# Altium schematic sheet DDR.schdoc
size 420 x 297 mm; Symbol: Drawing-Symbol_A4; Company: 嘉立创EDA; Version: V1.0; Page Size: A4; @Project Name: A113 Android MircroPhone; @Page Count: 4; @Update Date: 2025-09-30; @Create Date: 2025-08-09; @Schematic Name: Schematic1; @Page No: 2; @Page Name: DDR; @Create Time: 14:16:37; @Update Time: 17:41:18; Border: 1; Width: 1655; Height: 1170; Region Start: 1; X Region Count: 6; Y Region Count: 4; Blade Width: 10; Title Block Position: 3; @Board Name: Board1; Device: Drawing-Symbol_A4
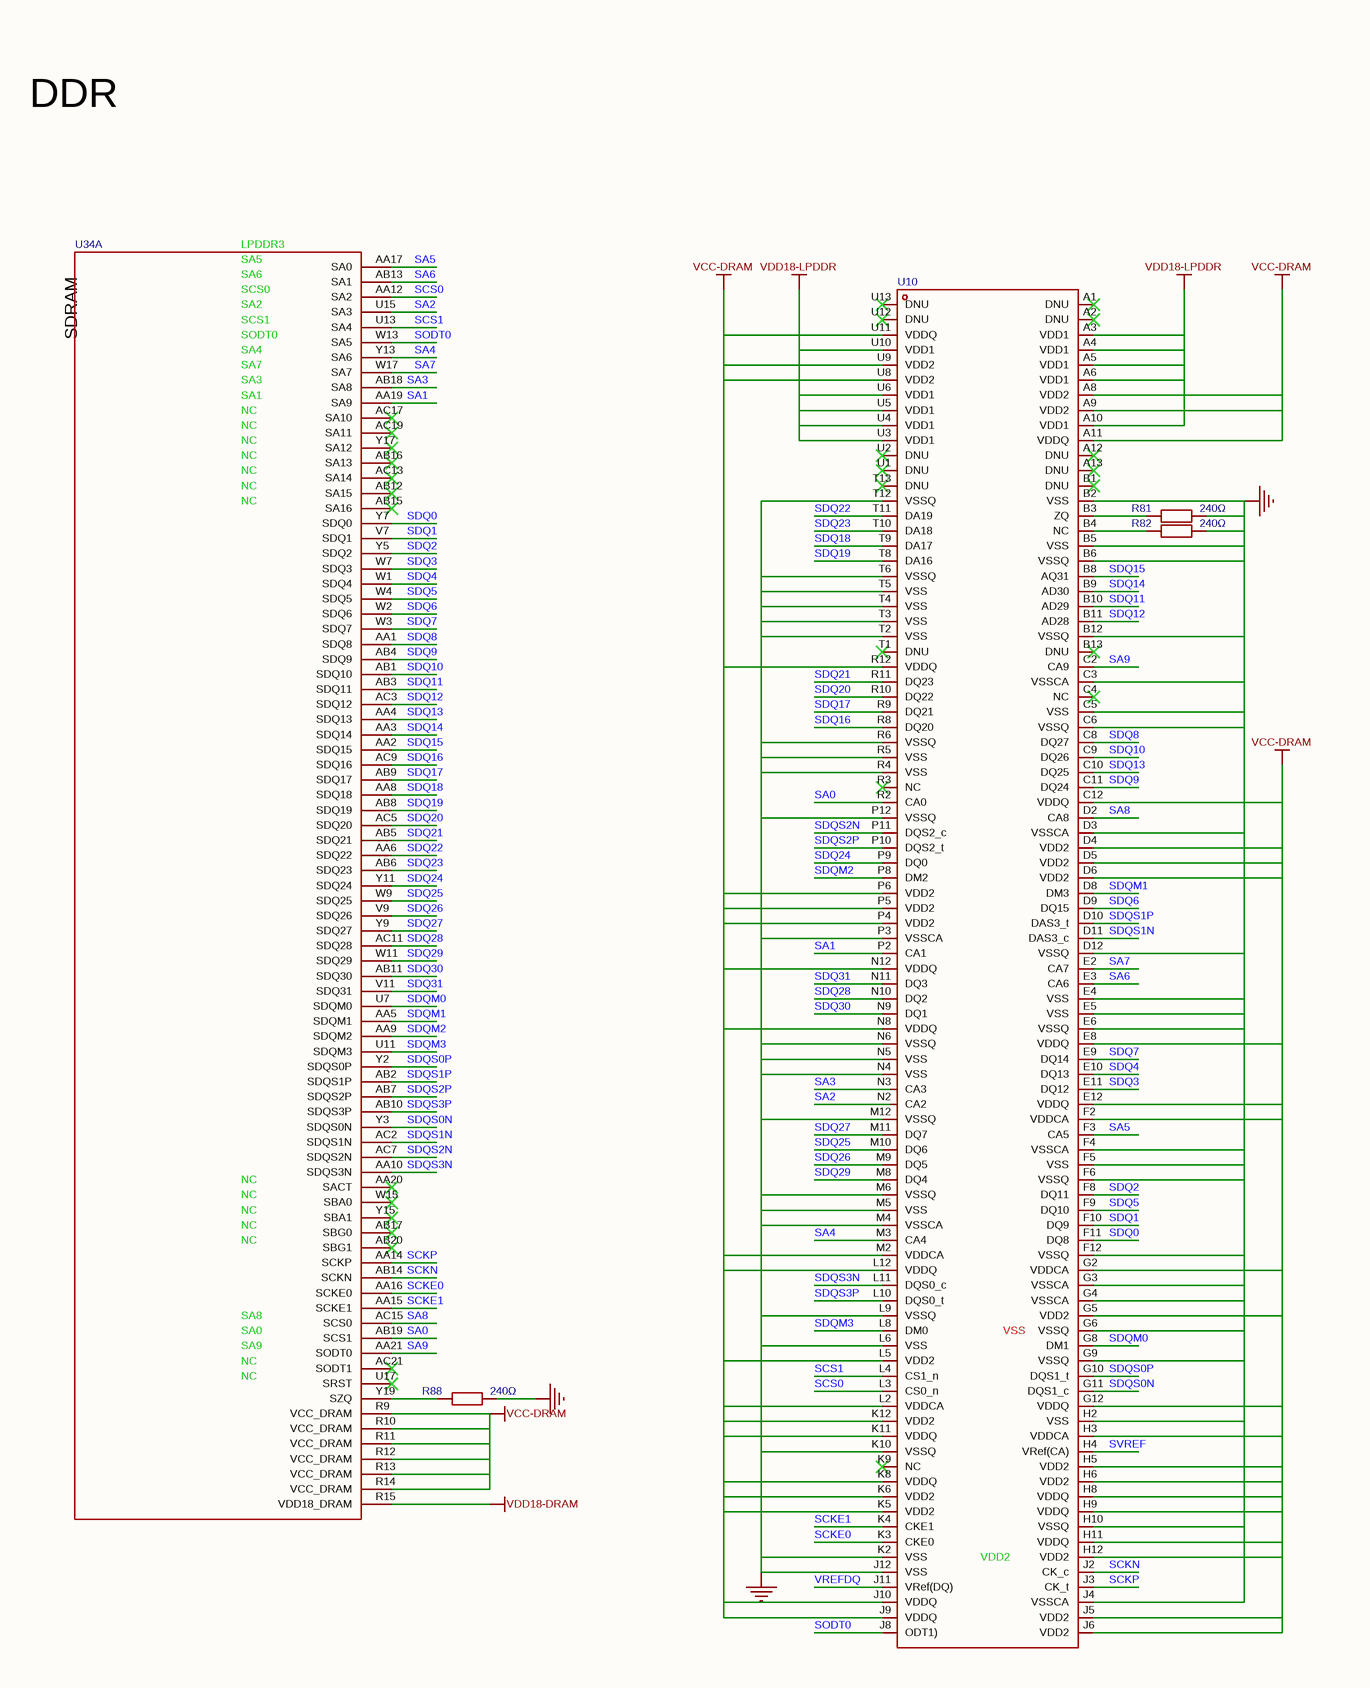
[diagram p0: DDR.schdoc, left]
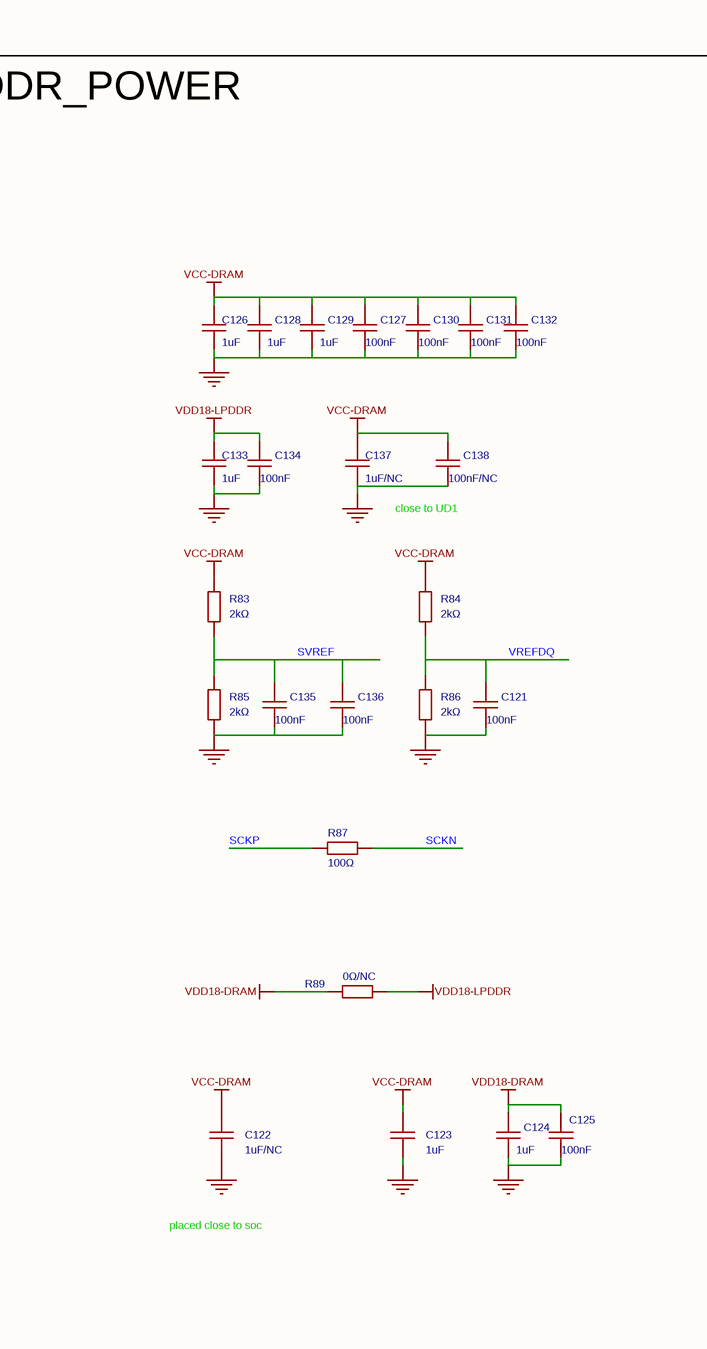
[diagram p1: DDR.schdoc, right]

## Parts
C121  100nF  [C0402]
C122  1uF/NC  [C0402]
C123  1uF  [C0402]
C124  1uF  [C0402]
C125  100nF  [C0402]
C126  1uF  [C0402]
C127  100nF  [C0402]
C128  1uF  [C0402]
C129  1uF  [C0402]
C130  100nF  [C0402]
C131  100nF  [C0402]
C132  100nF  [C0402]
C133  1uF  [C0402]
C134  100nF  [C0402]
C135  100nF  [C0402]
C136  100nF  [C0402]
C137  1uF/NC  [C0402]
C138  100nF/NC  [C0402]
R81  value 240Ω  [R0402]  (hidden comment: RC0402FR-07240RL)
R82  value 240Ω  [R0402]  (hidden comment: RC0402FR-07240RL)
R83  value 2kΩ  [R0402]  (hidden comment: RC0402FR-072KL)
R84  2kΩ  [R0402]
R85  value 2kΩ  [R0402]  (hidden comment: RC0402FR-072KL)
R86  2kΩ  [R0402]
R87  value 100Ω  [R0402]  (hidden comment: RC0402FR-07100RL)
R88  240Ω  [R0402]
R89  0Ω/NC  [R0402]
U10  K4E6E304ED-EGCG  [FBGA-178_L11.5-W11.0_MT52L256M32D1PF]  (value not drawn)
U34  A133  [LFBGA-346_L12.0-W12.0-P0.50-TL_ALLWINNER_A133]  (value not drawn)  (part A of 17)

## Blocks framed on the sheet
DDR_POWER: C121-C138 R83-R87 R89

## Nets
GND: C121.1 C122.2 C123.2 C124.2 C125.1 C126.2 C127.1 C128.2 C129.2 C130.1 C131.1 C132.1 C133.2 C134.1 C135.1 C136.1 C137.2 C138.1 R81.2 R82.2 R85.1 R86.1 R88.2 U10.B2(VSS) U10.B5(VSS) U10.B6(VSSQ) U10.B12(VSSQ) U10.C3(VSSCA) U10.C5(VSS) U10.C6(VSSQ) U10.D3(VSSCA) U10.D12(VSSQ) U10.E4(VSS) U10.E5(VSS) U10.E6(VSSQ) U10.F4(VSSCA) U10.F5(VSS) U10.F6(VSSQ) U10.F12(VSSQ) U10.G3(VSSCA) U10.G4(VSSCA) U10.G6(VSSQ) U10.G9(VSSQ) U10.H2(VSS) U10.H10(VSSQ) U10.J4(VSSCA) U10.J12(VSS) U10.K2(VSS) U10.K10(VSSQ) U10.L6(VSS) U10.L9(VSSQ) U10.M4(VSSCA) U10.M5(VSS) U10.M6(VSSQ) U10.M12(VSSQ) U10.N4(VSS) U10.N5(VSS) U10.N6(VSSQ) U10.P3(VSSCA) U10.P12(VSSQ) U10.R4(VSS) U10.R5(VSS) U10.R6(VSSQ) U10.T2(VSS) U10.T3(VSS) U10.T4(VSS) U10.T5(VSS) U10.T6(VSSQ) U10.T12(VSSQ)
VCC-DRAM: C122.1 C123.1 C126.1 C127.2 C128.1 C129.1 C130.2 C131.2 C132.2 C137.1 C138.2 R83.2 R84.2 U10.A8(VDD2) U10.A9(VDD2) U10.A11(VDDQ) U10.C12(VDDQ) U10.D4(VDD2) U10.D5(VDD2) U10.D6(VDD2) U10.E8(VDDQ) U10.E12(VDDQ) U10.F2(VDDCA) U10.G2(VDDCA) U10.G5(VDD2) U10.G12(VDDQ) U10.H3(VDDCA) U10.H5(VDD2) U10.H6(VDD2) U10.H8(VDDQ) U10.H9(VDDQ) U10.H11(VDDQ) U10.H12(VDD2) U10.J5(VDD2) U10.J6(VDD2) U10.J9(VDDQ) U10.J10(VDDQ) U10.K5(VDD2) U10.K6(VDD2) U10.K8(VDDQ) U10.K11(VDDQ) U10.K12(VDD2) U10.L2(VDDCA) U10.L5(VDD2) U10.L12(VDDQ) U10.M2(VDDCA) U10.N8(VDDQ) U10.N12(VDDQ) U10.P4(VDD2) U10.P5(VDD2) U10.P6(VDD2) U10.R12(VDDQ) U10.U8(VDD2) U10.U9(VDD2) U10.U11(VDDQ) U34.R9(VCC_DRAM) U34.R10(VCC_DRAM) U34.R11(VCC_DRAM) U34.R12(VCC_DRAM) U34.R13(VCC_DRAM) U34.R14(VCC_DRAM)
VDD18-DRAM: C124.1 C125.2 R89.1 U34.R15(VDD18_DRAM)
VDD18-LPDDR: C133.1 C134.2 R89.2 U10.A3(VDD1) U10.A4(VDD1) U10.A5(VDD1) U10.A6(VDD1) U10.A10(VDD1) U10.U3(VDD1) U10.U4(VDD1) U10.U5(VDD1) U10.U6(VDD1) U10.U10(VDD1)
SA0: U10.R2(CA0) U34.AB19(SCS1)
SA1: U10.P2(CA1) U34.AA19(SA9)
SA2: U10.N2(CA2) U34.U15(SA3)
SA3: U10.N3(CA3) U34.AB18(SA8)
SA4: U10.M3(CA4) U34.Y13(SA6)
SA5: U10.F3(CA5) U34.AA17(SA0)
SA6: U10.E3(CA6) U34.AB13(SA1)
SA7: U10.E2(CA7) U34.W17(SA7)
SA8: U10.D2(CA8) U34.AC15(SCS0)
SA9: U10.C2(CA9) U34.AA21(SODT0)
SCKE0: U10.K3(CKE0) U34.AA16(SCKE0)
SCKE1: U10.K4(CKE1) U34.AA15(SCKE1)
SCKN: R87.2 U10.J2(CK_c) U34.AB14(SCKN)
SCKP: R87.1 U10.J3(CK_t) U34.AA14(SCKP)
SCS0: U10.L3(CS0_n) U34.AA12(SA2)
SCS1: U10.L4(CS1_n) U34.U13(SA4)
SDQ0: U10.F11(DQ8) U34.Y7(SDQ0)
SDQ1: U10.F10(DQ9) U34.V7(SDQ1)
SDQ2: U10.F8(DQ11) U34.Y5(SDQ2)
SDQ3: U10.E11(DQ12) U34.W7(SDQ3)
SDQ4: U10.E10(DQ13) U34.W1(SDQ4)
SDQ5: U10.F9(DQ10) U34.W4(SDQ5)
SDQ6: U10.D9(DQ15) U34.W2(SDQ6)
SDQ7: U10.E9(DQ14) U34.W3(SDQ7)
SDQ8: U10.C8(DQ27) U34.AA1(SDQ8)
SDQ9: U10.C11(DQ24) U34.AB4(SDQ9)
SDQ10: U10.C9(DQ26) U34.AB1(SDQ10)
SDQ11: U10.B10(AD29) U34.AB3(SDQ11)
SDQ12: U10.B11(AD28) U34.AC3(SDQ12)
SDQ13: U10.C10(DQ25) U34.AA4(SDQ13)
SDQ14: U10.B9(AD30) U34.AA3(SDQ14)
SDQ15: U10.B8(AQ31) U34.AA2(SDQ15)
SDQ16: U10.R8(DQ20) U34.AC9(SDQ16)
SDQ17: U10.R9(DQ21) U34.AB9(SDQ17)
SDQ18: U10.T9(DA17) U34.AA8(SDQ18)
SDQ19: U10.T8(DA16) U34.AB8(SDQ19)
SDQ20: U10.R10(DQ22) U34.AC5(SDQ20)
SDQ21: U10.R11(DQ23) U34.AB5(SDQ21)
SDQ22: U10.T11(DA19) U34.AA6(SDQ22)
SDQ23: U10.T10(DA18) U34.AB6(SDQ23)
SDQ24: U10.P9(DQ0) U34.Y11(SDQ24)
SDQ25: U10.M10(DQ6) U34.W9(SDQ25)
SDQ26: U10.M9(DQ5) U34.V9(SDQ26)
SDQ27: U10.M11(DQ7) U34.Y9(SDQ27)
SDQ28: U10.N10(DQ2) U34.AC11(SDQ28)
SDQ29: U10.M8(DQ4) U34.W11(SDQ29)
SDQ30: U10.N9(DQ1) U34.AB11(SDQ30)
SDQ31: U10.N11(DQ3) U34.V11(SDQ31)
SDQM0: U10.G8(DM1) U34.U7(SDQM0)
SDQM1: U10.D8(DM3) U34.AA5(SDQM1)
SDQM2: U10.P8(DM2) U34.AA9(SDQM2)
SDQM3: U10.L8(DM0) U34.U11(SDQM3)
SDQS0N: U10.G11(DQS1_c) U34.Y3(SDQS0N)
SDQS0P: U10.G10(DQS1_t) U34.Y2(SDQS0P)
SDQS1N: U10.D11(DAS3_c) U34.AC2(SDQS1N)
SDQS1P: U10.D10(DAS3_t) U34.AB2(SDQS1P)
SDQS2N: U10.P11(DQS2_c) U34.AC7(SDQS2N)
SDQS2P: U10.P10(DQS2_t) U34.AB7(SDQS2P)
SDQS3N: U10.L11(DQS0_c) U34.AA10(SDQS3N)
SDQS3P: U10.L10(DQS0_t) U34.AB10(SDQS3P)
SODT0: U10.J8(ODT1)) U34.W13(SA5)
SVREF: C135.2 C136.2 R83.1 R85.2 U10.H4(VRef(CA))
VREFDQ: C121.2 R84.1 R86.2 U10.J11(VRef(DQ))
NetR81_1: R81.1 U10.B3(ZQ)
NetR82_1: R82.1 U10.B4(NC)
NetR88_1: R88.1 U34.Y19(SZQ)

Not connected (* = marked no-connect by the designer): U10 A1(DNU)* A2(DNU)* A12(DNU)* A13(DNU)* B1(DNU)* B13(DNU)* C4(NC)* K9(NC)* R3(NC)* T1(DNU)* T13(DNU)* U1(DNU)* U2(DNU)* U12(DNU)* U13(DNU)*; U34 AA20(SACT)* AB12(SA15)* AB15(SA16)* AB16(SA13)* AB17(SBG0)* AB20(SBG1)* AC13(SA14)* AC17(SA10)* AC19(SA11)* AC21(SODT1)* U17(SRST)* W15(SBA0)* Y15(SBA1)* Y17(SA12)*

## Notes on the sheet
- DDR
- LPDDR3
- SA5
- SA6
- SCS0
- SA2
- SODT0
- SA4
- SA7
- SA3
- SCS1
- NC
- SA1
- close to UD1
- placed close to soc
- SA8
- SA0
- SA9
- (near U10) VSS
- (near U10) VDD2

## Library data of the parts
C121 C125 C127 C130-C132 C134-C136 = CL05B104KO5NNNC: 容值:100nF;精度:±10%;额定电压:16V;材质(温度系数):X7R;; Manufacturer: SAMSUNG(三星); AddInBom: yes; ModelId: 36a51122f27c49738f86b3bfa98863e0; ModelName: C0402_L1.0-W0.5-H0.5; ModelTransform: 39.37,19.685,0,0,0,0,0,0,0; Tolerance: ±10%; Voltage Rated: 16V; Temperature Coefficient: X7R
C122 C137 = CL05A105KP5NNNC: 容值:1uF;精度:±10%;额定电压:10V;材质(温度系数):X5R;; Manufacturer: SAMSUNG(三星); Symbol: CL05A105KA5NQNC; Standardization Check: false; AddInBom: yes; ModelId: 36a51122f27c49738f86b3bfa98863e0; ModelName: C0402_L1.0-W0.5-H0.5; ModelTransform: 39.37,19.685,0,0,0,0,0,0,0; Tolerance: ±10%; Voltage Rated: 10V; Temperature Coefficient: X5R
C123 C124 C126 C128 C129 C133 = CL05A105KA5NQNC: 容值:1uF;精度:±10%;额定电压:25V;材质(温度系数):X5R;; Manufacturer: SAMSUNG(三星); Symbol: CL05A105KP5NNNC; AddInBom: yes; ModelId: 36a51122f27c49738f86b3bfa98863e0; ModelName: C0402_L1.0-W0.5-H0.5; ModelTransform: 39.37,19.685,0,0,0,0,0,0,0; Tolerance: ±10%; Voltage Rated: 25V; Temperature Coefficient: X5R
C138 = CL05B104KO5NNNC: 容值:100nF;精度:±10%;额定电压:16V;材质(温度系数):X7R;; Manufacturer: SAMSUNG(三星); Standardization Check: false; AddInBom: yes; ModelId: 36a51122f27c49738f86b3bfa98863e0; ModelName: C0402_L1.0-W0.5-H0.5; ModelTransform: 39.37,19.685,0,0,0,0,0,0,0; Tolerance: ±10%; Voltage Rated: 16V; Temperature Coefficient: X7R
R81 R82 R88 = RC0402FR-07240RL: 电阻类型:厚膜电阻;阻值:240Ω;精度:±1%;功率:62.5mW;; Manufacturer: YAGEO(国巨); AddInBom: yes; ModelId: 671aefced39d4c318694bba8bd8efd39; ModelName: R0402_L1.0-W0.5-H0.5; ModelTransform: 39.37,19.685,0,0,0,0,0,0.0005,0; Tolerance: ±1%; Power(Watts): 62.5mW; Temperature Coefficient: ±100ppm/℃; Overload Voltage (Max): 50V
R83-R86 = RC0402FR-072KL: 电阻类型:厚膜电阻;阻值:2kΩ;精度:±1%;功率:62.5mW;; Manufacturer: YAGEO(国巨); AddInBom: yes; ModelId: 671aefced39d4c318694bba8bd8efd39; ModelName: R0402_L1.0-W0.5-H0.5; ModelTransform: 39.37,19.685,0,0,0,0,0,0.0005,0; Tolerance: ±1%; Power(Watts): 62.5mW; Temperature Coefficient: ±100ppm/℃; Overload Voltage (Max): 50V
R87 = RC0402FR-07100RL: 电阻类型:厚膜电阻;阻值:100Ω;精度:±1%;功率:62.5mW;; Manufacturer: YAGEO(国巨); AddInBom: yes; ModelId: 671aefced39d4c318694bba8bd8efd39; ModelName: R0402_L1.0-W0.5-H0.5; ModelTransform: 39.37,19.685,0,0,0,0,0,0.0005,0; Tolerance: ±1%; Power(Watts): 62.5mW; Temperature Coefficient: ±100ppm/℃; Overload Voltage (Max): 50V
R89 = RC0402JR-070RL: 电阻类型:厚膜电阻;阻值:0Ω;精度:-;功率:62.5mW;; Manufacturer: YAGEO(国巨); Standardization Check: false; AddInBom: yes; ModelId: 671aefced39d4c318694bba8bd8efd39; ModelName: R0402_L1.0-W0.5-H0.5; ModelTransform: 39.37,19.685,0,0,0,0,0,0.0005,0; Power(Watts): 62.5mW; Overload Voltage (Max): 50V
U10 = K4E6E304ED-EGCG: Manufacturer: SAMSUNG(三星半导体); AddInBom: yes; ModelId: 6f079297d581413493afa6bb918e9fb4; ModelTransform: 433.07,452.755,0,0,0,0,0,0,0
U34 = A133: CPU内核:-;CPU最大主频:-;程序存储容量:-;程序存储器类型:-;RAM总容量:-;GPIO端口数量:-;; Manufacturer: Allwinner(全志); AddInBom: yes; ModelId: fdc1d13f198041f4a5f47084645a4f81; ModelTransform: 472.44,472.44,0,0,0,0,0,0,0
